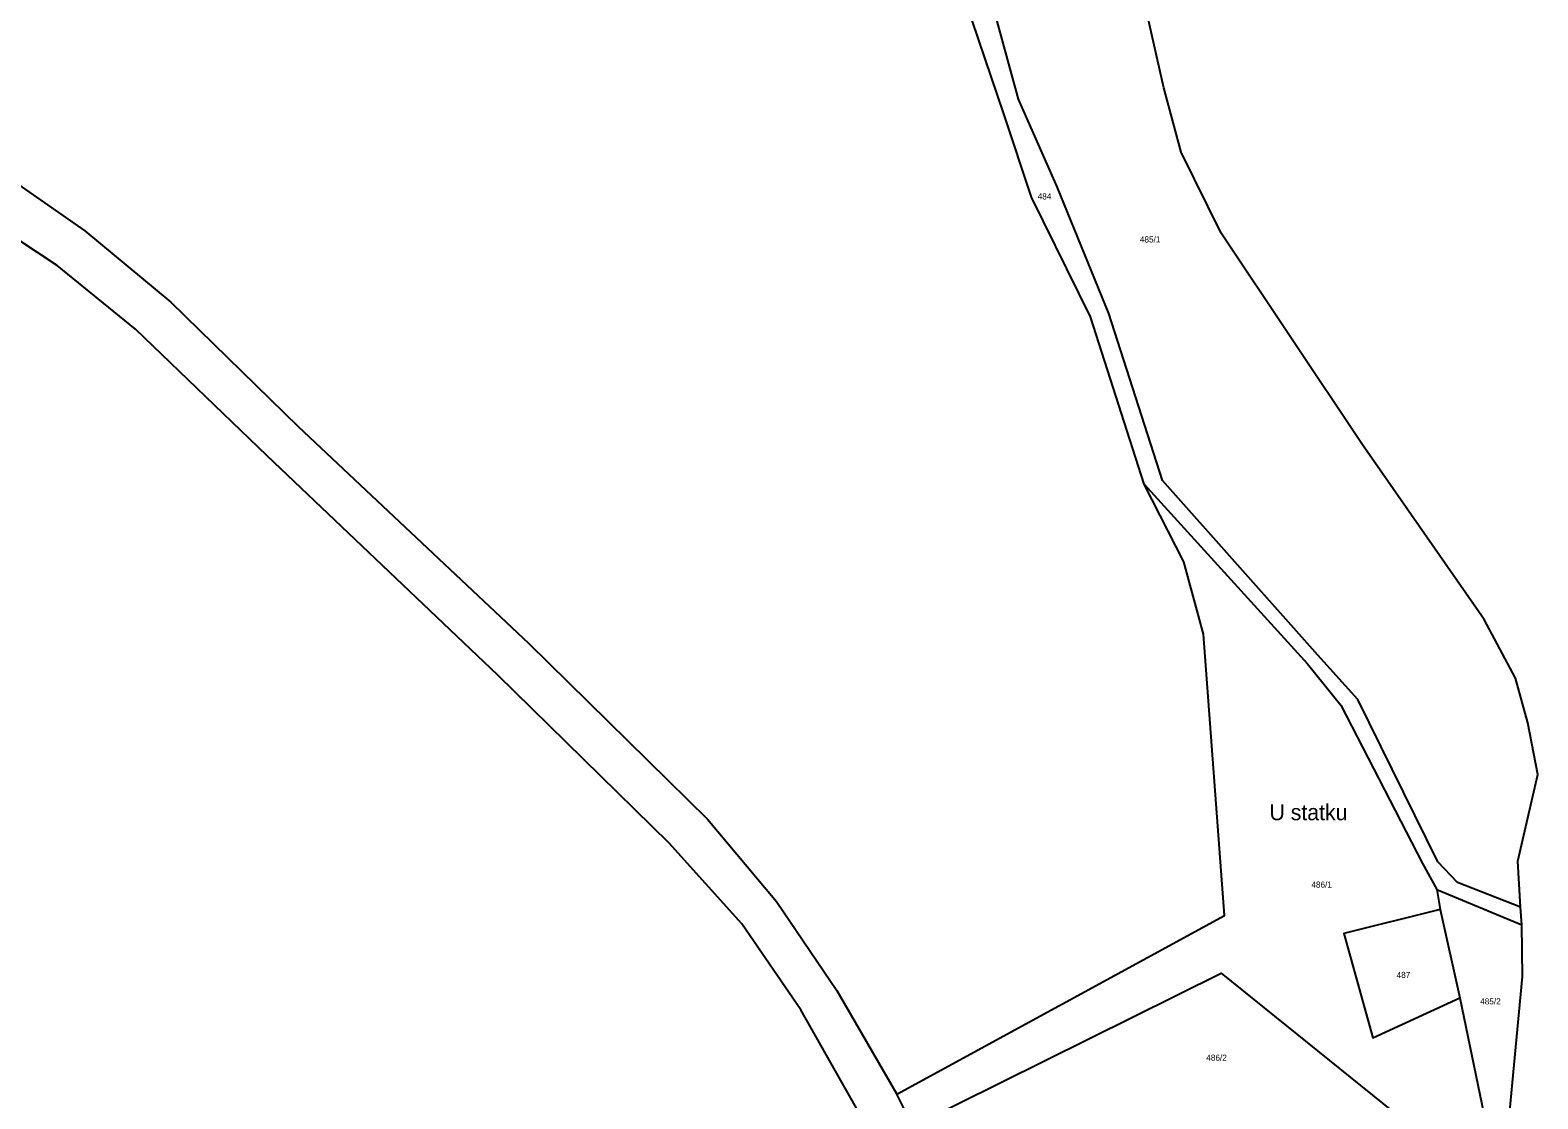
# Model space of a CAD drawing. Extents: x -880531 to -877616, y -1023932 to -1021350.
# Drawn here: x -878033.6 to -877616.3, y -1023264.8 to -1022969 of the extents above; entities that cross this region are included whole.
import ezdxf

# ---------------------------------------------------------------- set-up
doc = ezdxf.new("R2010")
doc.units = 0
for name, color, linetype in [('Hranice parcel', 7, 'Continuous'), ('Parcelní čísla', 7, 'Continuous'), ('Pop  PČ popisy', 7, 'Continuous')]:
    doc.layers.add(name, color=color, linetype=linetype)

msp = doc.modelspace()

# ---------------------------------------------------------------- linework, layer by layer
at = {"layer": 'Hranice parcel'}
for p, q in [((-877619.12, -1023160.69), (-877622.53, -1023148.32)), ((-877621.15, -1023211.68), (-877621.85, -1023199.03)), ((-877644.33, -1023206.86), (-877620.8, -1023216.59)), ((-877644.33, -1023206.86), (-877643.39, -1023212.36)), ((-877643.39, -1023212.36), (-877637.98, -1023236.8)), ((-877620.8, -1023216.59), (-877621.15, -1023211.68)), ((-877637.98, -1023236.8), (-877626.37, -1023292.54)), ((-877789.32, -1023272.27), (-877793.71, -1023263.48))]:
    msp.add_line(p, q, dxfattribs=at)
for points in [[(-878347.85, -1022769.53), (-878340.08, -1022772.06), (-878314.12, -1022786.74), (-878304.44, -1022794.02), (-878285.98, -1022807.27), (-878250.6, -1022834.52), (-878207.11, -1022875.3), (-878172.27, -1022910.11), (-878140.8, -1022940.6), (-878089.05, -1022975.4), (-878018.43, -1023024.57), (-877994.66, -1023044.33), (-877959.43, -1023078.68), (-877895.65, -1023138.67), (-877846.1, -1023187.34), (-877827.04, -1023210.17), (-877810.32, -1023234.77), (-877793.71, -1023263.48)], [(-877780.67, -1023314.89), (-877785.52, -1023301.59), (-877820.27, -1023240.12), (-877836.64, -1023216.31), (-877856.74, -1023193.96), (-877904.17, -1023147.51), (-877968.01, -1023086.79), (-878004.38, -1023051.82), (-878026.11, -1023034.14), (-878098.6, -1022986.3), (-878150.98, -1022948.79), (-878185.16, -1022918.23), (-878216.86, -1022884.4), (-878262.44, -1022844.37)], [(-877622.53, -1023148.32), (-877631.23, -1023132.13), (-877665.06, -1023083.5), (-877704.01, -1023025.26), (-877715.02, -1023002.83), (-877719.83, -1022985.04), (-877730.3, -1022938.89), (-877743.69, -1022881.75)], [(-877621.15, -1023211.68), (-877638.55, -1023204.88), (-877644, -1023199.18), (-877666.16, -1023154.23), (-877677.21, -1023141.97), (-877720.18, -1023093.69), (-877735.02, -1023047.41), (-877749.37, -1023012.36), (-877760.03, -1022988.13), (-877767.56, -1022960.87), (-877771.42, -1022948.07), (-877785.42, -1022926.1), (-877800.51, -1022904.53), (-877806.39, -1022896.9)], [(-877725.33, -1023094.7), (-877740.16, -1023048.4), (-877756.51, -1023015.22), (-877764.04, -1022992.5), (-877778.2, -1022950.55), (-877791.31, -1022927.33)], [(-877793.71, -1023263.48), (-877703.06, -1023214.02), (-877708.91, -1023136.2), (-877714.35, -1023116.15), (-877725.33, -1023094.7)], [(-877725.33, -1023094.7), (-877680.07, -1023144.34), (-877670.83, -1023155.84), (-877648.28, -1023199.59), (-877644.33, -1023206.86)], [(-877621.85, -1023199.03), (-877616.35, -1023174.96), (-877619.12, -1023160.69)], [(-877643.39, -1023212.36), (-877670, -1023219), (-877662.05, -1023247.91), (-877637.98, -1023236.8)], [(-877626.37, -1023292.54), (-877620.56, -1023230.87), (-877620.8, -1023216.59)], [(-877789.32, -1023272.27), (-877704.02, -1023230.02), (-877626.37, -1023292.54)]]:
    msp.add_lwpolyline(points, dxfattribs=at)

# ---------------------------------------------------------------- texts
at = {"layer": 'Parcelní čísla'}
for s, p in [('484', (-877754.76, -1023015.9)), ('485/1', (-877726.48, -1023027.8)), ('486/1', (-877679.02, -1023206.32)), ('487', (-877655.43, -1023231.31)), ('485/2', (-877632.31, -1023238.62)), ('486/2', (-877708.1, -1023254.21))]:
    msp.add_text(s, height=1.7, dxfattribs=at).set_placement(p)
at = {"layer": 'Pop  PČ popisy'}
msp.add_text('U statku', height=4.4, dxfattribs=at).set_placement((-877690.61, -1023187.66))

doc.saveas('drawing.dxf')
